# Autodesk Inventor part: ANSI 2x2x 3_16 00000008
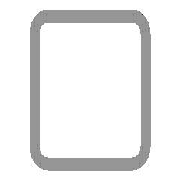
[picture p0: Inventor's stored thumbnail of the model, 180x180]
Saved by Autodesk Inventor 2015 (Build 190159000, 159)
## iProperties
IsCustomPart: 1
Created: 2007-02
Part Number: ANSI 2x2x 3_16 00000008
Material: Steel
Document SubType Name: Modeling
Standard: AISC
Designer: Autodesk, Inc.
Size Designation: 2x2x3/16
Stock Number: 2x2x 3/16
Density: 7.85 g/cm^3
Description: Tube
Standards Organization: ANSI
Language: en-US
Categories: <MemberInstance><Categories><Category DisplayName="Structural Shapes" InternalName="089c4875-fa83-4c05-b084-43b9cc11f5ed" Mnemonic="GRDR"><CategoryParameter Dis
Mass: 6278.25 g
Surface Area: 3375.01 cm^2
Volume: 799.777 cm^3
Appearance: Steel
G_L: 38.465 in
G_W: 2.000 in
G_H: 2.000 in
+635B083C-34CB-46B6-A37D-4BEAA1C5A815+CUTDETAIL1: Cut
_FrameMemberDoc: Frame Member File
_Version: 15.0.0
_CCFamilyMember: 1
_CCFamilyDisplayName: ANSI AISC (Square) - Tube
Author: Autodesk, Inc.
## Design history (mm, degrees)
node "Start plane"
node "End plane"
sketch "Sketch"
  geometry: L1 (-25.4, -15.875)-(-25.4, 15.875); L2 (-15.875, 25.4)-(15.875, 25.4); L3 (25.4, 15.875)-(25.4, -15.875); L4 (15.875, -25.4)-(-15.875, -25.4); L5 (-15.875, 20.637)-(15.875, 20.638); L6 (20.637, 15.875)-(20.637, -15.875); L7 (15.875, -20.637)-(-15.875, -20.638); L8 (-20.637, -15.875)-(-20.637, 15.875); L9 (0, 38.322)-(0, -38.322) reference; L10 (-38.322, 0)-(38.322, 0) reference; A1 r 9.525 centre (-15.875, -15.875) between (-25.4, -15.875) and (-15.875, -25.4); A2 r 9.525 centre (-15.875, 15.875) between (-15.875, 25.4) and (-25.4, 15.875); A3 r 9.525 centre (15.875, 15.875) between (25.4, 15.875) and (15.875, 25.4); A4 r 9.525 centre (15.875, -15.875) between (15.875, -25.4) and (25.4, -15.875); A5 r 4.762 centre (-15.875, 15.875) between (-15.875, 20.637) and (-20.637, 15.875); A6 r 4.762 centre (15.875, 15.875) between (20.637, 15.875) and (15.875, 20.638); A7 r 4.762 centre (15.875, -15.875) between (15.875, -20.637) and (20.637, -15.875); A8 r 4.762 centre (-15.875, -15.875) between (-20.637, -15.875) and (-15.875, -20.638)
  constraints: 16 end point, 16 point on circle, 8 centre point, 8 tangent, 4 parallel, 3 equal radius, 2 perpendicular, 7 other
  dimensions: "d10" = 50.8 distance between parallel lines of L2 L4 (= G_H); "d11" = 50.8 distance between parallel lines of L1 L3 (= G_W); "d12" = 4.7625 distance between parallel lines of L3 L6 (= G_T); "d15" = 25.4 distance between parallel lines of L2 L10 (= 0.5 x d10); "d16" = 25.4 distance between parallel lines of L9 L3 (= 0.5 x d11); "d17" = 9.525 radius of A1 (= G_IR)
extrude "Body" new body sketch "Sketch" stored distance "d3" = 977 (= G_L); taper "d4" = 0 deg
node "Driven Length"
  sketch "Sketch3"
    geometry: L1 (0, 0)-(10, 0) reference
    constraints: 2 end point, 1 horizontal
  workplane "Work Plane4"
  sketch "Sketch4"
    geometry: L1 (-2, -127)-(12, -127) reference; L2 (-2, 850)-(12, 850) reference
    dimensions: "d19" = 977 distance between parallel lines of L1 L2 (derived)
workplane "Work Plane3"
split "Split1"
body "Solid1"
other parameters: "G_W" = 50.8 [user parameter; used in 1 equation term], "G_H" = 50.8 [user parameter; used in 1 equation term], "G_T" = 4.7625 [user parameter; used in 1 equation term], "G_IR" = 9.525 [user parameter; used in 1 equation term], "G_L" = 977 (= d19) [user parameter; used in 1 equation term], "G_OFFSET_START" = 127 [user parameter; used in 1 equation term], "G_OFFSET_END" = 0 [user parameter; used in 1 equation term], "d13" = -127 (= -G_OFFSET_START), "d14" = 850 (= G_OFFSET_END + B_L), "B_L" = 850 [user parameter; used in 1 equation term], "d18" = 90 deg
